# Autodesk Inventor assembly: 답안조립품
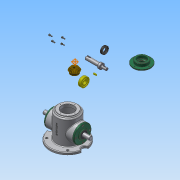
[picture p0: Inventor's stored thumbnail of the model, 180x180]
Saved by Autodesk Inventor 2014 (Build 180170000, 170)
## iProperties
Created: 2018-04
Part Number: 답안조립품
Document SubType Name: Assembly
Designer: user
Author: user
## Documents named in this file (16)
- C:\Users\user\Desktop\480407V1013\답안조립품.iam
- C:\Users\user\Desktop\480407V1013\본체.ipt
- C:\Users\user\Desktop\480407V1013\메인 베벨기어.ipt
- C:\Users\user\Desktop\480407V1013\메인 축.ipt
- 메인 축.ipt
- C:\Users\user\Desktop\480407V1013\베어링 6203.ipt
- C:\Users\user\Desktop\480407V1013\볼트 M4.ipt
- 볼트 M4.ipt
- C:\Users\user\Desktop\480407V1013\서브 베벨기어.ipt
- C:\Users\user\Desktop\480407V1013\서브 축.ipt
- 서브 축.ipt
- C:\Users\user\Desktop\480407V1013\오일 실.ipt
- 오일 실.ipt
- C:\Users\user\Desktop\480407V1013\커버.ipt
- C:\Users\user\Desktop\480407V1013\키 4x4.ipt
- C:\Users\user\Desktop\480407V1013\키 5x5.ipt
